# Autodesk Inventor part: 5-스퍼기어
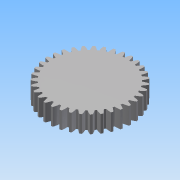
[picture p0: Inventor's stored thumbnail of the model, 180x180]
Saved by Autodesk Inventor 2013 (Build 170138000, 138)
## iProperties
Created: 2013-08
Part Number: 5-스퍼기어
Material: 강
Document SubType Name: Modeling
Designer: 한국산업디자인학원
Categories: <?xml version="1.0" encoding="UTF-16"?> <MemberInstance><Categories><FamilyTemplate><FamilyTemplateParameter ValueType="xs:double" Id="1" ObjectReferenceKey="da
Density: 1 g/cm^3
CustomPartVersion: 1
Author: 한국산업디자인학원
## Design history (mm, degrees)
sketch "Sketch1"
  geometry: C1 r 37 at (0, 0)
  constraints: 1 centre point
  dimensions: "d0" = 74 diameter of C1 (= da_da)
extrude "Extrusion1" new body sketch "Sketch1" distance "d1" = 15 (= da_b); taper "d2" = 0 deg
workplane "Work Plane2"
feature "피치 지름" dims "d4" = 10, "d5" = 0
workplane "Work Plane8"
workplane "Work Plane9"
feature "스퍼 기어" dims "da_b" = 15, "da_d" = 70, "da_aw" = 70, "da_da" = 74, "da_df" = 65, "da_dw" = 70, angle "da_beta" = 0 deg, "da_lefttooth" = 0, "da_righttooth" = 0
body "Solid1"
sketch "Sketch2"
  geometry: C1 r 37 at (0, 0) reference; C2 r 35 at (0, 0)
  constraints: 1 centre point, 1 coincident
  dimensions: "d3" = 70 diameter of C2 (= da_dw)
body "Srf1"
other parameters: "d17" = 0, "d34" = 0.8976 (computed from da_z), "d39" = 0, "d41" = 0, "d47" = 0, "d48" = 0
